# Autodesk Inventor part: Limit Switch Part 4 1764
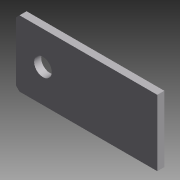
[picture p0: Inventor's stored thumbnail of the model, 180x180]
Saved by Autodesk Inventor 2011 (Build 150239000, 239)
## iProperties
Shininess: 0.0
Created: 2002-01
Part Number: Limit Switch Part 4 1764
Document SubType Name: Modeling
Density: 1 g/cm^3
Density: 0.0
Volumn: 0.0
Area: 0.0
PropertySet Name: Model Information
Control State: 0
Master: False
Checked Out: False
Author: Administrator
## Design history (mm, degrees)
node "Base1"
chamfer "Chamfer1" distance "d0" = 0.254; stored, may be unused: second distance "d1" = 3.175, angle "d2" = 45 deg
sketch "Sketch1"
  geometry: L1 (-9.906, 0)-(0, 0) reference; L2 (0, 4.75)-(-9.906, 4.75) reference; C1 r 0.635 at (-8.222, 2.375)
  constraints: 1 centre point
  dimensions: "d3" = 1.27 diameter of C1; "d4" = 4.7498 distance between parallel lines of L1 L2 (derived); "d5" = 2.3749 distance from line of L1 C1.centre (= 0.5 x d4)
extrude "Extrusion1" cut sketch "Sketch1" distance "d6" = 25.4; taper "d7" = 0 deg
body "Solid1"
